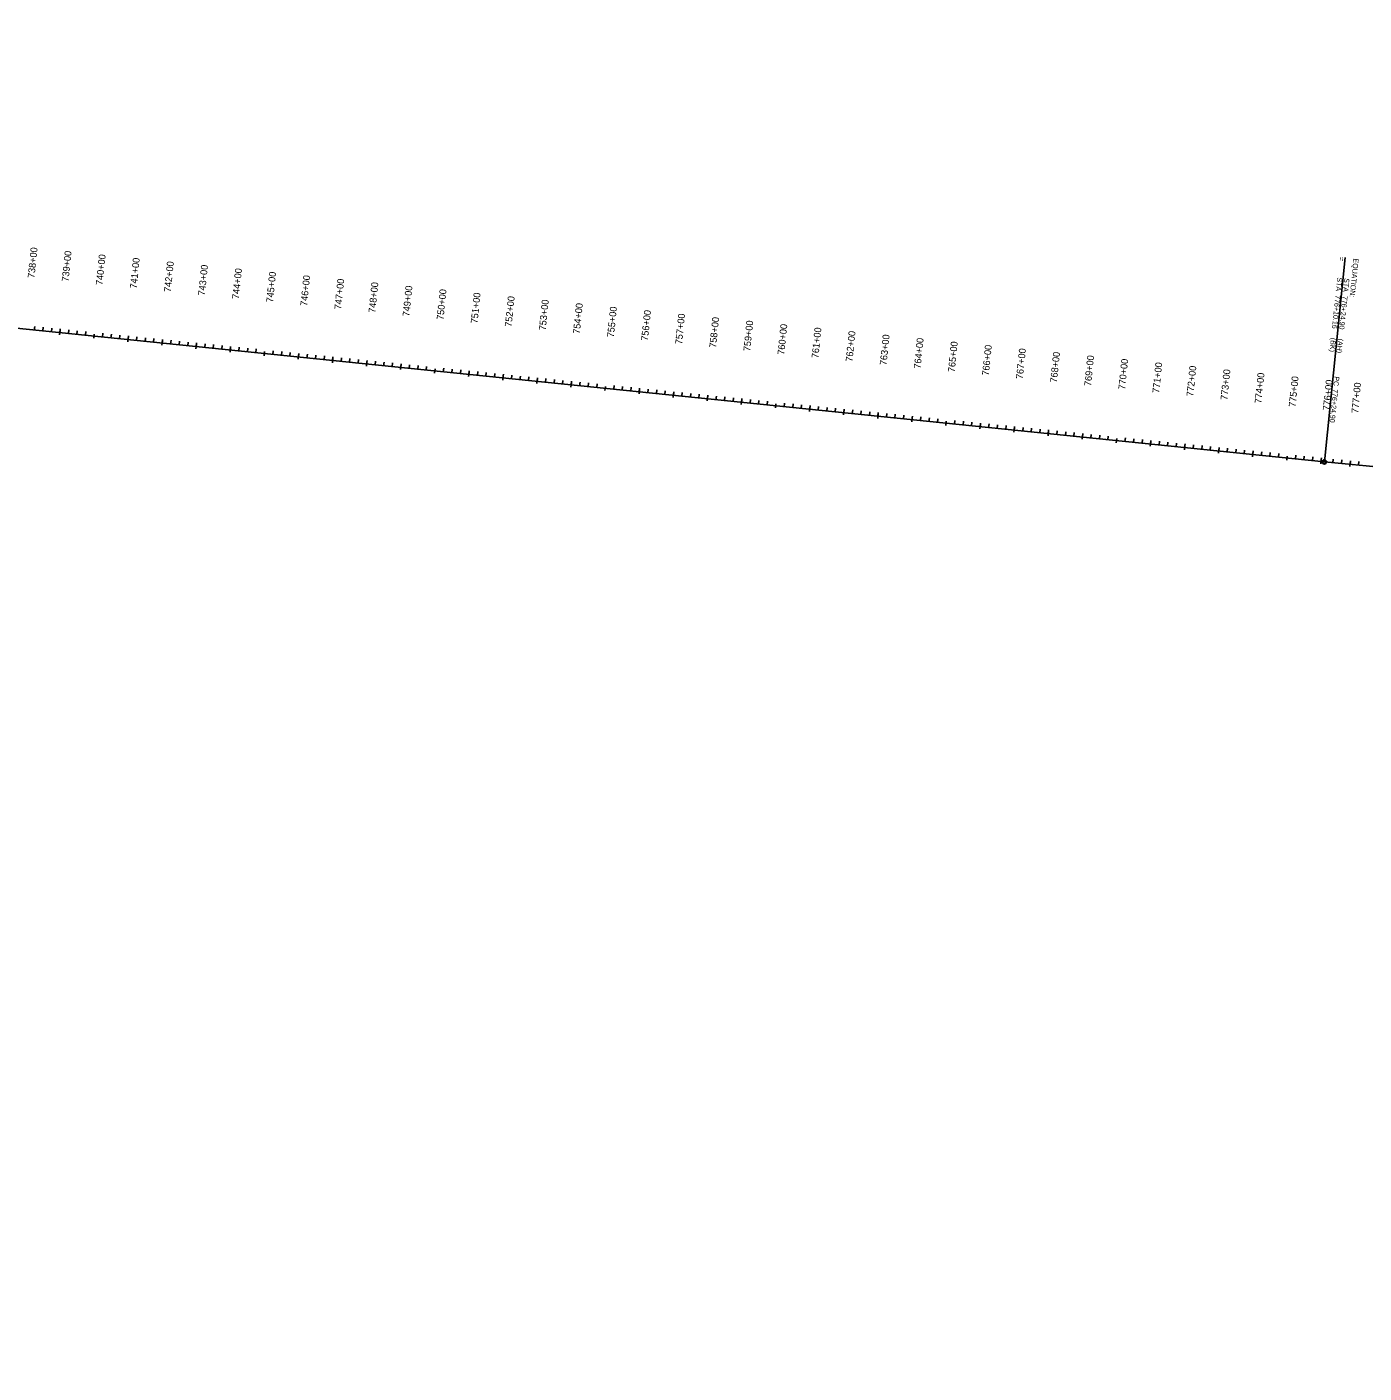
# Model space of a CAD drawing. Extents: x 22693007 to 22771804, y 6223023 to 6251673.
# Drawn here: x 22750890 to 22754793, y 6234805 to 6238732 of the extents above; entities that cross this region are included whole.
import ezdxf

# ---------------------------------------------------------------- set-up
doc = ezdxf.new("R2010")
doc.units = 0
for name, color, linetype in [('Default', 7, 'Continuous'), ('Draft_2', 7, 'Continuous'), ('NamedBoundary', 7, 'Continuous'), ('SheetBorder', 7, 'Continuous'), ('TextAlignment', 7, 'Continuous')]:
    doc.layers.add(name, color=color, linetype=linetype)

msp = doc.modelspace()

# ---------------------------------------------------------------- linework, layer by layer
at = {"layer": 'Default'}
msp.add_line((22748153.1, 6238129.7), (22754677, 6237463.3), dxfattribs=at)
msp.add_circle((22757478.8, 6237347.6), 14325, dxfattribs=at)
msp.add_arc((22755610.9, 6246605.8), 9190.1, 264.16759, 268.22188, dxfattribs=at)
at = {"layer": 'Draft_2'}
for p, q in [((22750986, 6237840.3), (22750987.1, 6237851.2)), ((22751086.1, 6237836.2), (22751084.9, 6237824.1)), ((22751185, 6237820), (22751186.1, 6237830.9)), ((22751284.5, 6237809.8), (22751285.6, 6237820.7)), ((22751384, 6237799.7), (22751385.1, 6237810.5)), ((22751483.4, 6237789.5), (22751484.5, 6237800.4)), ((22751583.5, 6237785.4), (22751582.3, 6237773.3)), ((22751682.4, 6237769.2), (22751683.5, 6237780)), ((22751781.9, 6237759), (22751783, 6237769.9)), ((22751881.4, 6237748.9), (22751882.5, 6237759.7)), ((22751980.8, 6237738.7), (22751982, 6237749.6)), ((22752081, 6237734.6), (22752079.7, 6237722.4)), ((22752179.8, 6237718.4), (22752180.9, 6237729.2)), ((22752279.3, 6237708.2), (22752280.4, 6237719.1)), ((22752378.8, 6237698.1), (22752379.9, 6237708.9)), ((22752478.3, 6237687.9), (22752479.4, 6237698.8)), ((22752578.4, 6237683.8), (22752577.1, 6237671.6)), ((22752677.2, 6237667.6), (22752678.3, 6237678.4)), ((22752776.7, 6237657.4), (22752777.8, 6237668.3)), ((22752876.2, 6237647.2), (22752877.3, 6237658.1)), ((22752975.7, 6237637.1), (22752976.8, 6237647.9)), ((22753075.8, 6237633), (22753074.5, 6237620.8)), ((22753174.6, 6237616.8), (22753175.7, 6237627.6)), ((22753274.1, 6237606.6), (22753275.2, 6237617.5)), ((22753373.6, 6237596.4), (22753374.7, 6237607.3)), ((22753473.1, 6237586.3), (22753474.2, 6237597.1)), ((22753573.2, 6237582.2), (22753571.9, 6237570)), ((22753672, 6237565.9), (22753673.2, 6237576.8)), ((22753771.5, 6237555.8), (22753772.6, 6237566.6)), ((22753871, 6237545.6), (22753872.1, 6237556.5)), ((22753970.5, 6237535.5), (22753971.6, 6237546.3)), ((22754070.6, 6237531.4), (22754069.4, 6237519.2)), ((22754169.5, 6237515.1), (22754170.6, 6237526)), ((22754268.9, 6237505), (22754270.1, 6237515.8)), ((22754368.4, 6237494.8), (22754369.5, 6237505.7)), ((22754467.9, 6237484.7), (22754469, 6237495.5)), ((22754568, 6237480.6), (22754566.8, 6237468.4)), ((22754666.9, 6237464.3), (22754668, 6237475.2)), ((22754751.7, 6237456), (22754752.7, 6237466.8))]:
    msp.add_line(p, q, dxfattribs=at)
at = {"layer": 'NamedBoundary'}
msp.add_line((22748153.1, 6238129.7), (22754677, 6237463.3), dxfattribs=at)
msp.add_arc((22755610.9, 6246605.8), 9190.1, 264.16759, 268.22188, dxfattribs=at)
at = {"layer": 'SheetBorder'}
for p, q in [((22750911.4, 6237847.9), (22750912.5, 6237858.8)), ((22750936.3, 6237845.4), (22750937.4, 6237856.3)), ((22750961.2, 6237842.9), (22750962.3, 6237853.7)), ((22750986.6, 6237846.4), (22750985.4, 6237834.2)), ((22751010.9, 6237837.8), (22751012, 6237848.6)), ((22751035.8, 6237835.2), (22751036.9, 6237846.1)), ((22751060.6, 6237832.7), (22751061.7, 6237843.6)), ((22751086.1, 6237836.2), (22751084.9, 6237824.1)), ((22751110.4, 6237827.6), (22751111.5, 6237838.5)), ((22751135.2, 6237825.1), (22751136.4, 6237835.9)), ((22751160.1, 6237822.5), (22751161.2, 6237833.4)), ((22751185.6, 6237826.1), (22751184.4, 6237813.9)), ((22751209.9, 6237817.5), (22751211, 6237828.3)), ((22751234.7, 6237814.9), (22751235.8, 6237825.8)), ((22751259.6, 6237812.4), (22751260.7, 6237823.2)), ((22751285.1, 6237815.9), (22751283.9, 6237803.7)), ((22751309.3, 6237807.3), (22751310.5, 6237818.2)), ((22751334.2, 6237804.8), (22751335.3, 6237815.6)), ((22751359.1, 6237802.2), (22751360.2, 6237813.1)), ((22751384.6, 6237805.8), (22751383.3, 6237793.6)), ((22751408.8, 6237797.1), (22751409.9, 6237808)), ((22751433.7, 6237794.6), (22751434.8, 6237805.5)), ((22751458.6, 6237792), (22751459.7, 6237802.9)), ((22751484.1, 6237795.6), (22751482.8, 6237783.4)), ((22751508.3, 6237787), (22751509.4, 6237797.8)), ((22751533.2, 6237784.4), (22751534.3, 6237795.3)), ((22751558, 6237781.9), (22751559.2, 6237792.8)), ((22751583.5, 6237785.4), (22751582.3, 6237773.3)), ((22751607.8, 6237776.8), (22751608.9, 6237787.7)), ((22751632.7, 6237774.3), (22751633.8, 6237785.1)), ((22751657.5, 6237771.7), (22751658.6, 6237782.6)), ((22751683, 6237775.3), (22751681.8, 6237763.1)), ((22751707.3, 6237766.6), (22751708.4, 6237777.5)), ((22751732.1, 6237764.1), (22751733.3, 6237775)), ((22751757, 6237761.6), (22751758.1, 6237772.4)), ((22751782.5, 6237765.1), (22751781.3, 6237752.9)), ((22751806.8, 6237756.5), (22751807.9, 6237767.3)), ((22751831.6, 6237753.9), (22751832.7, 6237764.8)), ((22751856.5, 6237751.4), (22751857.6, 6237762.3)), ((22751882, 6237754.9), (22751880.7, 6237742.8)), ((22751906.2, 6237746.3), (22751907.3, 6237757.2)), ((22751931.1, 6237743.8), (22751932.2, 6237754.6)), ((22751956, 6237741.2), (22751957.1, 6237752.1)), ((22751981.5, 6237744.8), (22751980.2, 6237732.6)), ((22752005.7, 6237736.2), (22752006.8, 6237747)), ((22752030.6, 6237733.6), (22752031.7, 6237744.5)), ((22752055.5, 6237731.1), (22752056.6, 6237741.9)), ((22752081, 6237734.6), (22752079.7, 6237722.4)), ((22752105.2, 6237726), (22752106.3, 6237736.9)), ((22752130.1, 6237723.5), (22752131.2, 6237734.3)), ((22752154.9, 6237720.9), (22752156.1, 6237731.8)), ((22752180.4, 6237724.5), (22752179.2, 6237712.3)), ((22752204.7, 6237715.8), (22752205.8, 6237726.7)), ((22752229.6, 6237713.3), (22752230.7, 6237724.2)), ((22752254.4, 6237710.8), (22752255.5, 6237721.6)), ((22752279.9, 6237714.3), (22752278.7, 6237702.1)), ((22752304.2, 6237705.7), (22752305.3, 6237716.5)), ((22752329, 6237703.1), (22752330.1, 6237714)), ((22752353.9, 6237700.6), (22752355, 6237711.5)), ((22752379.4, 6237704.1), (22752378.2, 6237692)), ((22752403.6, 6237695.5), (22752404.8, 6237706.4)), ((22752428.5, 6237693), (22752429.6, 6237703.8)), ((22752453.4, 6237690.4), (22752454.5, 6237701.3)), ((22752478.9, 6237694), (22752477.6, 6237681.8)), ((22752503.1, 6237685.3), (22752504.2, 6237696.2)), ((22752528, 6237682.8), (22752529.1, 6237693.7)), ((22752552.9, 6237680.3), (22752554, 6237691.1)), ((22752578.4, 6237683.8), (22752577.1, 6237671.6)), ((22752602.6, 6237675.2), (22752603.7, 6237686.1)), ((22752627.5, 6237672.6), (22752628.6, 6237683.5)), ((22752652.4, 6237670.1), (22752653.5, 6237681)), ((22752677.8, 6237673.7), (22752676.6, 6237661.5)), ((22752702.1, 6237665), (22752703.2, 6237675.9)), ((22752727, 6237662.5), (22752728.1, 6237673.3)), ((22752751.8, 6237659.9), (22752752.9, 6237670.8)), ((22752801.6, 6237654.9), (22752802.7, 6237665.7)), ((22752777.3, 6237663.5), (22752776.1, 6237651.3)), ((22752826.4, 6237652.3), (22752827.6, 6237663.2)), ((22752851.3, 6237649.8), (22752852.4, 6237660.6)), ((22752876.8, 6237653.3), (22752875.6, 6237641.2)), ((22752901.1, 6237644.7), (22752902.2, 6237655.6)), ((22752925.9, 6237642.2), (22752927, 6237653)), ((22752950.8, 6237639.6), (22752951.9, 6237650.5)), ((22752976.3, 6237643.2), (22752975, 6237631)), ((22753000.5, 6237634.5), (22753001.7, 6237645.4)), ((22753025.4, 6237632), (22753026.5, 6237642.9)), ((22753050.3, 6237629.5), (22753051.4, 6237640.3)), ((22753075.8, 6237633), (22753074.5, 6237620.8)), ((22753100, 6237624.4), (22753101.1, 6237635.2)), ((22753124.9, 6237621.8), (22753126, 6237632.7)), ((22753149.8, 6237619.3), (22753150.9, 6237630.2)), ((22753199.5, 6237614.2), (22753200.6, 6237625.1)), ((22753175.3, 6237622.8), (22753174, 6237610.7)), ((22753224.4, 6237611.7), (22753225.5, 6237622.5)), ((22753249.2, 6237609.1), (22753250.4, 6237620)), ((22753274.7, 6237612.7), (22753273.5, 6237600.5)), ((22753299, 6237604.1), (22753300.1, 6237614.9)), ((22753323.9, 6237601.5), (22753325, 6237612.4)), ((22753348.7, 6237599), (22753349.8, 6237609.8)), ((22753374.2, 6237602.5), (22753373, 6237590.3)), ((22753398.5, 6237593.9), (22753399.6, 6237604.8)), ((22753423.3, 6237591.4), (22753424.5, 6237602.2)), ((22753448.2, 6237588.8), (22753449.3, 6237599.7)), ((22753473.7, 6237592.4), (22753472.5, 6237580.2)), ((22753498, 6237583.7), (22753499.1, 6237594.6)), ((22753522.8, 6237581.2), (22753523.9, 6237592.1)), ((22753547.7, 6237578.6), (22753548.8, 6237589.5)), ((22753573.2, 6237582.2), (22753571.9, 6237570)), ((22753597.4, 6237573.6), (22753598.5, 6237584.4)), ((22753622.3, 6237571), (22753623.4, 6237581.9)), ((22753647.2, 6237568.5), (22753648.3, 6237579.4)), ((22753672.7, 6237572), (22753671.4, 6237559.9)), ((22753696.9, 6237563.4), (22753698, 6237574.3)), ((22753721.8, 6237560.9), (22753722.9, 6237571.7)), ((22753746.7, 6237558.3), (22753747.8, 6237569.2)), ((22753772.2, 6237561.9), (22753770.9, 6237549.7)), ((22753796.4, 6237553.2), (22753797.5, 6237564.1)), ((22753821.3, 6237550.7), (22753822.4, 6237561.6)), ((22753846.1, 6237548.2), (22753847.3, 6237559)), ((22753871.6, 6237551.7), (22753870.4, 6237539.5)), ((22753895.9, 6237543.1), (22753897, 6237553.9)), ((22753920.8, 6237540.5), (22753921.9, 6237551.4)), ((22753945.6, 6237538), (22753946.7, 6237548.9)), ((22753971.1, 6237541.5), (22753969.9, 6237529.4)), ((22753995.4, 6237532.9), (22753996.5, 6237543.8)), ((22754020.2, 6237530.4), (22754021.3, 6237541.2)), ((22754045.1, 6237527.8), (22754046.2, 6237538.7)), ((22754070.6, 6237531.4), (22754069.4, 6237519.2)), ((22754094.8, 6237522.8), (22754096, 6237533.6)), ((22754119.7, 6237520.2), (22754120.8, 6237531.1)), ((22754144.6, 6237517.7), (22754145.7, 6237528.5)), ((22754170.1, 6237521.2), (22754168.8, 6237509)), ((22754194.3, 6237512.6), (22754195.4, 6237523.5)), ((22754219.2, 6237510.1), (22754220.3, 6237520.9)), ((22754244.1, 6237507.5), (22754245.2, 6237518.4)), ((22754269.6, 6237511.1), (22754268.3, 6237498.9)), ((22754293.8, 6237502.4), (22754294.9, 6237513.3)), ((22754318.7, 6237499.9), (22754319.8, 6237510.8)), ((22754343.6, 6237497.4), (22754344.7, 6237508.2)), ((22754369, 6237500.9), (22754367.8, 6237488.7)), ((22754393.3, 6237492.3), (22754394.4, 6237503.1)), ((22754418.2, 6237489.7), (22754419.3, 6237500.6)), ((22754443, 6237487.2), (22754444.1, 6237498.1)), ((22754468.5, 6237490.7), (22754467.3, 6237478.6)), ((22754492.8, 6237482.1), (22754493.9, 6237493)), ((22754517.6, 6237479.6), (22754518.8, 6237490.4)), ((22754542.5, 6237477), (22754543.6, 6237487.9)), ((22754568, 6237480.6), (22754566.8, 6237468.4)), ((22754592.3, 6237471.9), (22754593.4, 6237482.8)), ((22754617.1, 6237469.4), (22754618.2, 6237480.3)), ((22754642, 6237466.9), (22754643.1, 6237477.7)), ((22754667.5, 6237470.4), (22754666.2, 6237458.2)), ((22754677.1, 6237463.3), (22754678.2, 6237474.1)), ((22754702, 6237460.8), (22754703, 6237471.6)), ((22754726.8, 6237458.3), (22754727.9, 6237469.2)), ((22754752.3, 6237462.1), (22754751.1, 6237449.9)), ((22754776.6, 6237453.7), (22754777.6, 6237464.5))]:
    msp.add_line(p, q, dxfattribs=at)
at = {"layer": 'TextAlignment'}
for p, q in [((22754677, 6237463.3), (22754738, 6238060.2)), ((22754738, 6238060.2), (22754738, 6238060.2)), ((22754677, 6237463.3), (22754702.6, 6237714)), ((22754702.6, 6237714), (22754702.6, 6237714))]:
    msp.add_line(p, q, dxfattribs=at)
for radius in [6.24, 5.34]:
    msp.add_circle((22754677, 6237463.3), radius, dxfattribs=at)

# ---------------------------------------------------------------- texts
at = {"layer": 'Draft_2'}
for s, p in [('740+00', (22751110.7, 6237978.4)), ('745+00', (22751608.1, 6237927.6)), ('750+00', (22752105.5, 6237876.7)), ('755+00', (22752603, 6237825.9)), ('760+00', (22753100.4, 6237775.1)), ('765+00', (22753597.8, 6237724.3)), ('770+00', (22754095.2, 6237673.5)), ('775+00', (22754592.6, 6237622.7))]:
    msp.add_text(s, height=20.04, rotation=84.1676, dxfattribs=at).set_placement(p)
at = {"layer": 'SheetBorder'}
for s, rotation, p in [('738+00', 84.1676, (22750911.8, 6237998.7)), ('739+00', 84.1676, (22751011.2, 6237988.5)), ('740+00', 84.1676, (22751110.7, 6237978.4)), ('741+00', 84.1676, (22751210.2, 6237968.2)), ('742+00', 84.1676, (22751309.7, 6237958)), ('743+00', 84.1676, (22751409.2, 6237947.9)), ('744+00', 84.1676, (22751508.6, 6237937.7)), ('745+00', 84.1676, (22751608.1, 6237927.6)), ('746+00', 84.1676, (22751707.6, 6237917.4)), ('747+00', 84.1676, (22751807.1, 6237907.2)), ('748+00', 84.1676, (22751906.6, 6237897.1)), ('749+00', 84.1676, (22752006.1, 6237886.9)), ('750+00', 84.1676, (22752105.5, 6237876.7)), ('751+00', 84.1676, (22752205, 6237866.6)), ('752+00', 84.1676, (22752304.5, 6237856.4)), ('753+00', 84.1676, (22752404, 6237846.3)), ('754+00', 84.1676, (22752503.5, 6237836.1)), ('755+00', 84.1676, (22752603, 6237825.9)), ('756+00', 84.1676, (22752702.4, 6237815.8)), ('757+00', 84.1676, (22752801.9, 6237805.6)), ('758+00', 84.1676, (22752901.4, 6237795.4)), ('759+00', 84.1676, (22753000.9, 6237785.3)), ('760+00', 84.1676, (22753100.4, 6237775.1)), ('761+00', 84.1676, (22753199.8, 6237765)), ('762+00', 84.1676, (22753299.3, 6237754.8)), ('763+00', 84.1676, (22753398.8, 6237744.6)), ('764+00', 84.1676, (22753498.3, 6237734.5)), ('765+00', 84.1676, (22753597.8, 6237724.3)), ('766+00', 84.1676, (22753697.3, 6237714.2)), ('767+00', 84.1676, (22753796.7, 6237704)), ('768+00', 84.1676, (22753896.2, 6237693.8)), ('769+00', 84.1676, (22753995.7, 6237683.7)), ('770+00', 84.1676, (22754095.2, 6237673.5)), ('771+00', 84.1676, (22754194.7, 6237663.3)), ('772+00', 84.1676, (22754294.2, 6237653.2)), ('773+00', 84.1676, (22754393.6, 6237643)), ('774+00', 84.1676, (22754493.1, 6237632.9)), ('775+00', 84.1676, (22754592.6, 6237622.7)), ('776+00', 84.1676, (22754692.1, 6237612.5)), ('777+00', 84.6358, (22754775.7, 6237604.4))]:
    msp.add_text(s, height=20.04, rotation=rotation, dxfattribs=at).set_placement(p)
at = {"layer": 'TextAlignment'}
for s, p in [('=', (22754720.4, 6238062)), ('EQUATION:', (22754762.1, 6238057.7)), ('STA ', (22754714.3, 6238002.3)), ('STA ', (22754735.2, 6238000.2)), ('776+10.16', (22754709, 6237950.6)), ('776+24.90', (22754729.9, 6237948.5)), ('(BK)', (22754696.2, 6237826)), ('(AH)', (22754717.1, 6237823.8)), ('PC', (22754705.9, 6237713.7)), ('776+24.90', (22754702.1, 6237676.5))]:
    msp.add_text(s, height=15, rotation=264.1676, dxfattribs=at).set_placement(p)

doc.saveas('drawing.dxf')
